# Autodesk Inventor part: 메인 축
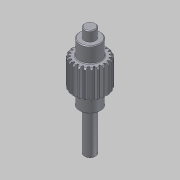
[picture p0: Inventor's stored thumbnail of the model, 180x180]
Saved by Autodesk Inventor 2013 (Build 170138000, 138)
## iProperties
Created: 2014-07
Part Number: 메인 축
Material: Steel
Document SubType Name: Modeling
Designer: KYOUNG IL JANG
Categories: <?xml version="1.0" encoding="UTF-16"?> <MemberInstance><Categories><FamilyTemplate><FamilyTemplateParameter ValueType="xs:double" Id="1" ObjectReferenceKey="da
Density: 1 g/cm^3
CustomPartVersion: 1
Company: 한국ATC센터
Author: KYOUNG IL JANG
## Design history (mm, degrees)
sketch "Sketch1"
  geometry: C1 r 12 at (0, 0)
  constraints: 1 centre point
  dimensions: "d0" = 24 diameter of C1 (= da_da)
extrude "Extrusion1" new body sketch "Sketch1" distance "d1" = 20 (= da_b); taper "d2" = 0 deg
workplane "Work Plane2"
sketch "Sketch2"
  geometry: C1 r 12 at (0, 0) reference; C2 r 11 at (0, 0)
  constraints: 1 centre point, 1 coincident
  dimensions: "d3" = 22 diameter of C2 (= da_dw)
feature "피치 지름" sketch "Sketch2" dims "d4" = 10, "d5" = 0
workplane "Work Plane8"
workplane "Work Plane9"
chamfer "모따기1" distance "d49" = 1; stored, may be unused: second distance "d50" = 2, angle "d51" = 45 deg
sketch "스케치3"
  geometry: C1 r 7.5 at (0, 0); 1 further point
  constraints: 1 centre point, 1 coincident
  dimensions: "d52" = 15 diameter of C1
extrude "돌출2" join sketch "스케치3" distance "d53" = 11; taper "d54" = 0 deg
sketch "스케치4"
  geometry: C1 r 4 at (0, 0); 1 further point
  constraints: 1 centre point, 1 coincident
  dimensions: "d55" = 8 diameter of C1
extrude "돌출3" join sketch "스케치4" distance "d56" = 7; taper "d57" = 0 deg
sketch "스케치5"
  geometry: C1 r 7.5 at (0, 0) reference; C2 r 7.5 at (0, 0) reference; 1 further point
extrude "돌출4" join sketch "스케치5" distance "d62" = 11; taper "d63" = 0 deg
sketch "스케치6"
  geometry: C1 r 4 at (0, 0); 1 further point
  constraints: 1 centre point, 1 coincident
  dimensions: "d64" = 8 diameter of C1
extrude "돌출5" join sketch "스케치6" distance "d65" = 30; taper "d66" = 0 deg
chamfer "모따기2" distance "d58" = 0.5; stored, may be unused: second distance "d59" = 2, angle "d60" = 45 deg
fillet "모깎기1" dims "d61" = 0.5
feature "스퍼 기어" dims "da_b" = 20, "da_d" = 22, "da_aw" = 31, "da_da" = 24, "da_df" = 19.5, "da_dw" = 22, angle "da_beta" = 0 deg, "da_lefttooth" = 0, "da_righttooth" = 0
body "Solid1"
body "Srf1"
node "투영된 루프1"
other parameters: "d16" = 31 (= da_aw), "d17" = 0, "d34" = 1.428 (computed from da_z), "d39" = 0, "d41" = 0, "d43" = 31 (= da_aw), "d46" = 31 (= da_aw), "d47" = 0, "d48" = 0
